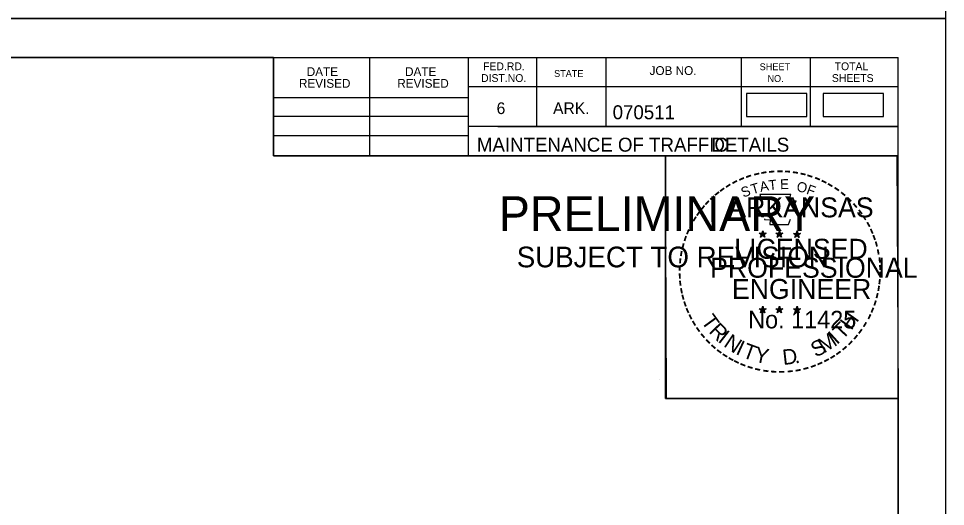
# Model space of a CAD drawing. Extents: x 1398460 to 1408037, y 380768 to 383968.
# Drawn here: x 1403534.1 to 1403998.9, y 382656.3 to 382900.9 of the extents above; entities that cross this region are included whole.
import ezdxf

# ---------------------------------------------------------------- set-up
doc = ezdxf.new("R2010")
doc.units = 0
for name, color, linetype in [('R_Border', 7, 'Continuous'), ('R_Border PE', 7, 'Continuous'), ('R_Border Prem', 7, 'Continuous'), ('R_Dimension', 7, 'Continuous'), ('R_No Plot', 7, 'Continuous')]:
    doc.layers.add(name, color=color, linetype=linetype)

msp = doc.modelspace()

# ---------------------------------------------------------------- linework, layer by layer
at = {"layer": 'R_Border'}
for p, q in [((1402394.27, 382881.42), (1403975.17, 382881.42)), ((1403661.97, 382832.02), (1403661.97, 382881.42)), ((1403710.37, 382832.02), (1403710.37, 382881.42)), ((1403759.67, 382881.42), (1403759.67, 382832.02)), ((1403793.87, 382881.42), (1403793.87, 382846.72)), ((1403828.57, 382881.42), (1403828.57, 382846.72)), ((1403896.47, 382881.42), (1403896.47, 382846.72)), ((1403931.17, 382881.42), (1403931.17, 382846.72)), ((1403975.17, 381854.12), (1403975.17, 382881.42)), ((1403975.17, 382866.72), (1403759.67, 382866.72)), ((1403975.17, 382866.82), (1403975.17, 382866.82)), ((1403661.97, 382861.32), (1403759.67, 382861.32)), ((1403661.97, 382852.02), (1403759.67, 382852.02)), ((1403975.17, 382846.72), (1403759.67, 382846.72)), ((1403774.47, 382846.72), (1403975.17, 382846.72)), ((1403661.97, 382842.32), (1403759.67, 382842.32)), ((1403975.17, 382832.02), (1403661.97, 382832.02))]:
    msp.add_line(p, q, dxfattribs=at)
at = {"layer": 'R_Border PE'}
for p, q in [((1403907.34, 382794.56), (1403907.13, 382793.3)), ((1403907.34, 382792.74), (1403907.34, 382794.56)), ((1403907.34, 382794.56), (1403907.58, 382793.31)), ((1403915.69, 382794.56), (1403915.48, 382793.3)), ((1403915.69, 382792.74), (1403915.69, 382794.56)), ((1403915.69, 382794.56), (1403915.93, 382793.31)), ((1403924.51, 382794.5), (1403924.3, 382793.24)), ((1403924.51, 382792.68), (1403924.51, 382794.5)), ((1403924.51, 382794.5), (1403924.75, 382793.25)), ((1403905.59, 382793.29), (1403907.34, 382792.74)), ((1403905.59, 382793.29), (1403906.86, 382793.07)), ((1403905.59, 382793.29), (1403906.78, 382792.68)), ((1403906.26, 382791.25), (1403907.34, 382792.74)), ((1403906.26, 382791.25), (1403906.89, 382792.47)), ((1403906.26, 382791.25), (1403907.33, 382792.34)), ((1403908.4, 382791.25), (1403907.33, 382792.32)), ((1403909.07, 382793.29), (1403907.34, 382792.74)), ((1403908.4, 382791.25), (1403907.34, 382792.74)), ((1403909.07, 382793.29), (1403907.64, 382793.05)), ((1403908.4, 382791.25), (1403907.72, 382792.71)), ((1403909.07, 382793.29), (1403908.05, 382792.78)), ((1403913.94, 382793.29), (1403915.69, 382792.74)), ((1403913.94, 382793.29), (1403915.21, 382793.07)), ((1403913.94, 382793.29), (1403915.13, 382792.68)), ((1403914.61, 382791.25), (1403915.69, 382792.74)), ((1403914.61, 382791.25), (1403915.24, 382792.47)), ((1403914.61, 382791.25), (1403915.68, 382792.34)), ((1403916.75, 382791.25), (1403915.68, 382792.32)), ((1403917.42, 382793.29), (1403915.69, 382792.74)), ((1403916.75, 382791.25), (1403915.69, 382792.74)), ((1403917.42, 382793.29), (1403915.99, 382793.05)), ((1403916.75, 382791.25), (1403916.07, 382792.71)), ((1403917.42, 382793.29), (1403916.4, 382792.78)), ((1403922.76, 382793.23), (1403924.51, 382792.68)), ((1403922.76, 382793.23), (1403924.03, 382793.01)), ((1403922.76, 382793.23), (1403923.95, 382792.62)), ((1403923.43, 382791.19), (1403924.51, 382792.68)), ((1403923.43, 382791.19), (1403924.06, 382792.41)), ((1403923.43, 382791.19), (1403924.5, 382792.28)), ((1403925.57, 382791.19), (1403924.5, 382792.26)), ((1403926.24, 382793.23), (1403924.51, 382792.68)), ((1403925.57, 382791.19), (1403924.51, 382792.68)), ((1403926.24, 382793.23), (1403924.81, 382792.99)), ((1403925.57, 382791.19), (1403924.89, 382792.65)), ((1403926.24, 382793.23), (1403925.22, 382792.72)), ((1403905.57, 382755.43), (1403907.32, 382754.87)), ((1403905.57, 382755.43), (1403906.84, 382755.2)), ((1403905.57, 382755.43), (1403906.76, 382754.82)), ((1403906.24, 382753.39), (1403907.32, 382754.87)), ((1403906.24, 382753.39), (1403906.87, 382754.61)), ((1403906.24, 382753.39), (1403907.31, 382754.47)), ((1403907.32, 382756.7), (1403907.11, 382755.44)), ((1403908.38, 382753.39), (1403907.31, 382754.46)), ((1403907.32, 382754.87), (1403907.32, 382756.7)), ((1403907.32, 382756.7), (1403907.56, 382755.45)), ((1403909.05, 382755.43), (1403907.32, 382754.87)), ((1403908.38, 382753.39), (1403907.32, 382754.87)), ((1403909.05, 382755.43), (1403907.62, 382755.18)), ((1403908.38, 382753.39), (1403907.7, 382754.84)), ((1403909.05, 382755.43), (1403908.03, 382754.92)), ((1403913.92, 382755.43), (1403915.66, 382754.87)), ((1403913.92, 382755.43), (1403915.18, 382755.2)), ((1403913.92, 382755.43), (1403915.1, 382754.82)), ((1403914.58, 382753.39), (1403915.66, 382754.87)), ((1403914.58, 382753.39), (1403915.21, 382754.61)), ((1403914.58, 382753.39), (1403915.65, 382754.47)), ((1403915.66, 382756.7), (1403915.46, 382755.44)), ((1403916.73, 382753.39), (1403915.65, 382754.46)), ((1403915.66, 382754.87), (1403915.66, 382756.7)), ((1403915.66, 382756.7), (1403915.91, 382755.45)), ((1403917.4, 382755.43), (1403915.66, 382754.87)), ((1403916.73, 382753.39), (1403915.66, 382754.87)), ((1403917.4, 382755.43), (1403915.97, 382755.18)), ((1403916.73, 382753.39), (1403916.04, 382754.84)), ((1403917.4, 382755.43), (1403916.38, 382754.92)), ((1403922.75, 382755.38), (1403924.5, 382754.82)), ((1403922.75, 382755.38), (1403924.02, 382755.15)), ((1403922.75, 382755.38), (1403923.94, 382754.77)), ((1403923.42, 382753.34), (1403924.5, 382754.82)), ((1403923.42, 382753.34), (1403924.05, 382754.56)), ((1403923.42, 382753.34), (1403924.49, 382754.42)), ((1403924.5, 382756.65), (1403924.29, 382755.39)), ((1403925.56, 382753.34), (1403924.49, 382754.41)), ((1403924.5, 382754.82), (1403924.5, 382756.65)), ((1403924.5, 382756.65), (1403924.74, 382755.4)), ((1403926.23, 382755.38), (1403924.5, 382754.82)), ((1403925.56, 382753.34), (1403924.5, 382754.82)), ((1403926.23, 382755.38), (1403924.8, 382755.13)), ((1403925.56, 382753.34), (1403924.88, 382754.79)), ((1403926.23, 382755.38), (1403925.21, 382754.87))]:
    msp.add_line(p, q, dxfattribs=at)
for points in [[(1403905.8, 382812.68), (1403907.14, 382808.55)], [(1403923.35, 382808.07), (1403924.06, 382809.49), (1403920.64, 382809.37), (1403921.38, 382812.68), (1403905.8, 382812.68)], [(1403908.26, 382800.57), (1403908.26, 382800.13), (1403911.07, 382800.04), (1403910.8, 382797.67), (1403920.15, 382797.67), (1403921.16, 382800.35)], [(1403907.34, 382794.56), (1403908.4, 382791.25), (1403905.59, 382793.29), (1403909.07, 382793.29), (1403906.26, 382791.25), (1403907.34, 382794.56)], [(1403915.69, 382794.56), (1403916.75, 382791.25), (1403913.94, 382793.29), (1403917.42, 382793.29), (1403914.61, 382791.25), (1403915.69, 382794.56)], [(1403924.51, 382794.5), (1403925.57, 382791.19), (1403922.76, 382793.23), (1403926.24, 382793.23), (1403923.43, 382791.19), (1403924.51, 382794.5)], [(1403907.32, 382756.7), (1403908.38, 382753.39), (1403905.57, 382755.43), (1403909.05, 382755.43), (1403906.24, 382753.39), (1403907.32, 382756.7)], [(1403915.66, 382756.7), (1403916.73, 382753.39), (1403913.92, 382755.43), (1403917.4, 382755.43), (1403914.58, 382753.39), (1403915.66, 382756.7)], [(1403924.5, 382756.65), (1403925.56, 382753.34), (1403922.75, 382755.38), (1403926.23, 382755.38), (1403923.42, 382753.34), (1403924.5, 382756.65)]]:
    msp.add_lwpolyline(points, dxfattribs=at)
for centre, radius in [((1403907.33, 382792.73), 0.861), ((1403907.33, 382792.73), 0.723), ((1403907.33, 382792.73), 0.579), ((1403907.33, 382792.73), 0.495), ((1403907.33, 382792.73), 0.374), ((1403907.33, 382792.73), 0.248), ((1403907.33, 382792.73), 0.148), ((1403915.68, 382792.73), 0.861), ((1403915.68, 382792.73), 0.723), ((1403915.68, 382792.73), 0.579), ((1403915.68, 382792.73), 0.495), ((1403915.68, 382792.73), 0.374), ((1403915.68, 382792.73), 0.248), ((1403915.68, 382792.73), 0.148), ((1403924.5, 382792.67), 0.861), ((1403924.5, 382792.67), 0.723), ((1403924.5, 382792.67), 0.579), ((1403924.5, 382792.67), 0.495), ((1403924.5, 382792.67), 0.374), ((1403924.5, 382792.67), 0.248), ((1403924.5, 382792.67), 0.148), ((1403907.31, 382754.87), 0.861), ((1403907.31, 382754.87), 0.723), ((1403907.31, 382754.87), 0.579), ((1403907.31, 382754.87), 0.495), ((1403907.31, 382754.87), 0.374), ((1403907.31, 382754.87), 0.248), ((1403907.31, 382754.87), 0.148), ((1403915.66, 382754.87), 0.861), ((1403915.66, 382754.87), 0.723), ((1403915.66, 382754.87), 0.579), ((1403915.66, 382754.87), 0.495), ((1403915.66, 382754.87), 0.374), ((1403915.66, 382754.87), 0.248), ((1403915.66, 382754.87), 0.148), ((1403924.49, 382754.82), 0.861), ((1403924.49, 382754.82), 0.723), ((1403924.49, 382754.82), 0.579), ((1403924.49, 382754.82), 0.495), ((1403924.49, 382754.82), 0.374), ((1403924.49, 382754.82), 0.248), ((1403924.49, 382754.82), 0.148)]:
    msp.add_circle(centre, radius, dxfattribs=at)
at = {"layer": 'R_Dimension'}
for points in [[(1403899.23, 382851.73), (1403929.5, 382851.73), (1403929.5, 382863.28), (1403899.23, 382863.28)], [(1403937.63, 382851.79), (1403967.9, 382851.79), (1403967.9, 382863.35), (1403937.63, 382863.35)]]:
    msp.add_lwpolyline(points, close=True, dxfattribs=at)
at = {"layer": 'R_No Plot'}
for p, q in [((1402332.26, 382900.89), (1403998.93, 382900.89)), ((1403855.34, 382719.74), (1403855.34, 382719.74))]:
    msp.add_line(p, q, dxfattribs=at)
for points in [[(1402332.23, 383967.58), (1403998.93, 383967.58), (1403998.93, 382900.89), (1402332.23, 382900.89)], [(1402332.23, 382900.89), (1403998.93, 382900.89), (1403998.93, 381834.2), (1402332.23, 381834.2)], [(1402394.27, 382881.42), (1402394.27, 381854.12), (1403975.17, 381854.12), (1403975.17, 382710.36), (1403858.52, 382710.36), (1403858.52, 382832.02), (1403661.97, 382832.02), (1403661.97, 382881.42)], [(1403563.87, 382881.42), (1403661.97, 382881.42), (1403661.97, 382832.02), (1403742.53, 382832.02), (1403858.52, 382832.02), (1403858.52, 382710.36), (1403975.17, 382710.36), (1403975.17, 381854.12), (1402394.27, 381854.12), (1402394.27, 382881.42)], [(1403858.52, 382832.02), (1403974.56, 382832.02), (1403975.17, 382710.36), (1403859.13, 382710.36)]]:
    msp.add_lwpolyline(points, close=True, dxfattribs=at)

# ---------------------------------------------------------------- texts
at = {"layer": 'R_Border'}
for s, height, p in [('FED.RD.', 3.91, (1403767.07, 382875.02)), ('SHEET', 3.42, (1403905.77, 382875.02)), ('TOTAL', 3.91, (1403943.37, 382875.02)), ('DATE', 4.396, (1403678.66, 382872.1)), ('DATE', 4.396, (1403727.96, 382872.1)), ('STATE', 3.42, (1403802.67, 382871.62)), ('JOB NO.', 4.396, (1403850.57, 382872.62)), ('REVISED', 4.396, (1403674.76, 382866.2)), ('REVISED', 4.396, (1403724.06, 382866.2)), ('DIST.NO.', 3.91, (1403766.07, 382869.12)), ('NO.', 3.42, (1403909.67, 382869.12)), ('SHEETS', 3.91, (1403941.97, 382869.12)), ('6', 5.86, (1403773.87, 382853.02)), ('ARK.', 5.861, (1403802.17, 382853.02)), ('070511', 7, (1403832.05, 382850.42)), ('MAINTENANCE OF TRAFFIC', 7, (1403763.98, 382834.17)), (' DETAILS', 7, (1403878.98, 382834.17))]:
    msp.add_text(s, height=height, dxfattribs=at).set_placement(p)
at = {"layer": 'R_Border PE'}
for s, height, rotation, p in [('-', 8, 19.1761, (1403899.54, 382818.32)), ('-', 8, 13.6302, (1403903.29, 382819.52)), ('-', 8, 10.2193, (1403906.68, 382820.33)), ('-', 8, 5.8968, (1403910.32, 382820.88)), ('-', 8, 0.1862, (1403914.18, 382821.24)), ('-', 8, 357.743, (1403917.8, 382821.18)), ('-', 8, 352.1617, (1403921.52, 382820.9)), ('-', 8, 347.2049, (1403925.11, 382820.33)), ('-', 8, 342.3362, (1403928.29, 382819.55)), ('-', 8, 34.0636, (1403890.22, 382813.54)), ('-', 8, 28.7918, (1403893.2, 382815.39)), ('-', 8, 24.3072, (1403896.37, 382816.97)), ('T', 5, 16.4036, (1403902.14, 382812.73)), ('A', 5, 11.2132, (1403906.27, 382813.98)), ('T', 5, 6.0228, (1403910.52, 382814.81)), ('E', 5, 0.8323, (1403916.04, 382815.36)), ('O', 5, 350.4515, (1403924.06, 382814.31)), ('F', 5, 340.0707, (1403928.83, 382813.17)), ('-', 8, 337.8551, (1403931.96, 382818.44)), ('-', 8, 334.1211, (1403935.12, 382817.08)), ('-', 8, 329.6409, (1403938.01, 382815.67)), ('-', 8, 38.9507, (1403884.95, 382809.67)), ('-', 8, 36.2317, (1403887.33, 382811.56)), ('S', 5, 21.594, (1403897.57, 382811.07)), ('-', 8, 325.8627, (1403941.23, 382813.86)), ('-', 8, 320.5297, (1403944.28, 382811.73)), ('-', 8, 48.4231, (1403880.54, 382805.2)), ('-', 8, 42.9622, (1403882.78, 382807.59)), ('-', 8, 315.5786, (1403947.27, 382809.29)), ('-', 8, 309.8797, (1403950.12, 382806.54)), ('-', 8, 54.2325, (1403876.46, 382799.93)), ('-', 8, 50.6142, (1403878.53, 382802.77)), ('-', 8, 306.6522, (1403952.74, 382803.53)), ('-', 8, 58.0706, (1403874.84, 382797.3)), ('-', 7, 303.6753, (1403955.17, 382800.69)), ('-', 8, 299.6684, (1403956.77, 382797.66)), ('-', 8, 67.7743, (1403871.98, 382791.17)), ('-', 8, 62.8713, (1403873.27, 382794.23)), ('-', 8, 294.6628, (1403958.39, 382794.6)), ('-', 8, 72.3945, (1403870.88, 382788.02)), ('-', 8, 290.5728, (1403959.67, 382791.71)), ('-', 8, 75.461, (1403869.9, 382784.45)), ('-', 8, 285.1233, (1403960.84, 382788.81)), ('-', 8, 280.5493, (1403961.84, 382785.1)), ('-', 8, 85.1863, (1403868.86, 382777.43)), ('-', 8, 81.2013, (1403869.24, 382780.89)), ('-', 8, 276.5962, (1403962.65, 382781.26)), ('-', 8, 89.0622, (1403868.73, 382773.93)), ('-', 8, 274.3301, (1403962.95, 382777.65)), ('-', 8, 94.1959, (1403868.91, 382770.3)), ('-', 8, 269.9407, (1403963.12, 382774.49)), ('-', 8, 98.9479, (1403869.27, 382766.97)), ('-', 8, 260.9953, (1403962.67, 382767.89)), ('-', 8, 263.5172, (1403963.03, 382771.16)), ('-', 8, 101.7149, (1403869.94, 382763.3)), ('-', 8, 105.4578, (1403870.75, 382760.33)), ('-', 8, 255.7626, (1403962.12, 382764.5)), ('-', 8, 109.0874, (1403871.83, 382757.17)), ('-', 8, 252.8681, (1403961.22, 382760.9)), ('-', 8, 114.0643, (1403873.1, 382754.19)), ('-', 8, 115.7289, (1403874.62, 382751.1)), ('T', 7.7, 306.0406, (1403876.11, 382749.06)), ('H', 7.7, 54.6088, (1403951.71, 382744.24)), ('-', 8, 244.6197, (1403958.79, 382754.39)), ('-', 8, 247.8887, (1403960.1, 382757.54)), ('-', 8, 120.4471, (1403876.41, 382748.17)), ('R', 7.7, 314.005, (1403879.93, 382743.83)), ('T', 7.7, 46.6444, (1403947.27, 382739.53)), ('-', 8, 239.0712, (1403956.82, 382750.63)), ('-', 8, 125.8934, (1403878.42, 382745.37)), ('-', 8, 130.7181, (1403880.73, 382742.61)), ('I', 7.7, 321.9694, (1403884.43, 382739.17)), ('M', 7.7, 32.6563, (1403938.04, 382732.9)), ('I', 7.7, 42.1136, (1403944.46, 382737.14)), ('-', 8, 233.8452, (1403954.81, 382747.37)), ('-', 8, 134.2238, (1403883.32, 382739.88)), ('N', 7.7, 326.5002, (1403887.26, 382736.81)), ('I', 7.7, 335.3603, (1403893.31, 382732.88)), ('S', 7.7, 26.9312, (1403933.84, 382730.87)), ('-', 8, 225.7653, (1403950.27, 382741.72)), ('-', 8, 231.2538, (1403952.66, 382744.54)), ('-', 8, 138.9338, (1403885.94, 382737.56)), ('-', 8, 144.6463, (1403888.72, 382735.53)), ('T', 7.7, 339.8912, (1403896.61, 382731.24)), ('Y', 7.7, 347.8556, (1403902.7, 382729.01)), ('D', 7.7, 6.3969, (1403917.62, 382727.22)), ('-', 8, 215.7363, (1403944.91, 382736.81)), ('-', 8, 221.0851, (1403947.66, 382739.17)), ('-', 8, 148.0898, (1403891.53, 382733.68)), ('-', 8, 151.5704, (1403894.42, 382732.05)), ('-', 8, 154.6002, (1403897.03, 382730.82)), ('.', 7.7, 13.7642, (1403923.58, 382727.86)), ('-', 8, 207.3568, (1403939.45, 382733.15)), ('-', 8, 212.2491, (1403942.24, 382734.88)), ('-', 8, 158.5612, (1403900.15, 382729.55)), ('-', 8, 162.7983, (1403903.59, 382728.48)), ('-', 8, 167.5555, (1403907.16, 382727.66)), ('-', 8, 173.1155, (1403911.02, 382727.11)), ('-', 8, 185.8167, (1403922.53, 382727.32)), ('-', 8, 191.2858, (1403926.21, 382727.98)), ('-', 8, 195.4743, (1403929.85, 382728.98)), ('-', 8, 200.7184, (1403933.24, 382730.19)), ('-', 8, 204.2516, (1403936.33, 382731.55)), ('-', 8, 176.5183, (1403914.76, 382726.85)), ('-', 8, 181.5918, (1403918.48, 382726.94))]:
    msp.add_text(s, height=height, rotation=rotation, dxfattribs=at).set_placement(p)
for s, height, p in [('ARKANSAS', 10, (1403890.06, 382801.24)), ('LICENSED', 10, (1403893.05, 382780.5)), ('DWB', 0.05, (1403907.27, 382792.71)), ('DWB', 0.05, (1403915.62, 382792.71)), ('DWB', 0.05, (1403924.44, 382792.66)), ('PROFESSIONAL', 10, (1403880.93, 382770.98)), ('ENGINEER', 10, (1403891.87, 382760.35)), ('No. 11425', 8.785, (1403900, 382745.6)), ('DWB', 0.05, (1403907.25, 382754.85)), ('DWB', 0.05, (1403915.6, 382754.85)), ('DWB', 0.05, (1403924.43, 382754.8))]:
    msp.add_text(s, height=height, dxfattribs=at).set_placement(p)
at = {"layer": 'R_Border Prem'}
for s, height, p in [('PRELIMINARY', 17.5, (1403774.92, 382794.33)), ('DWB', 0.05, (1403778.66, 382803.58)), ('SUBJECT TO REVISION', 10.3756, (1403783.97, 382776.19))]:
    msp.add_text(s, height=height, dxfattribs=at).set_placement(p)

doc.saveas('drawing.dxf')
